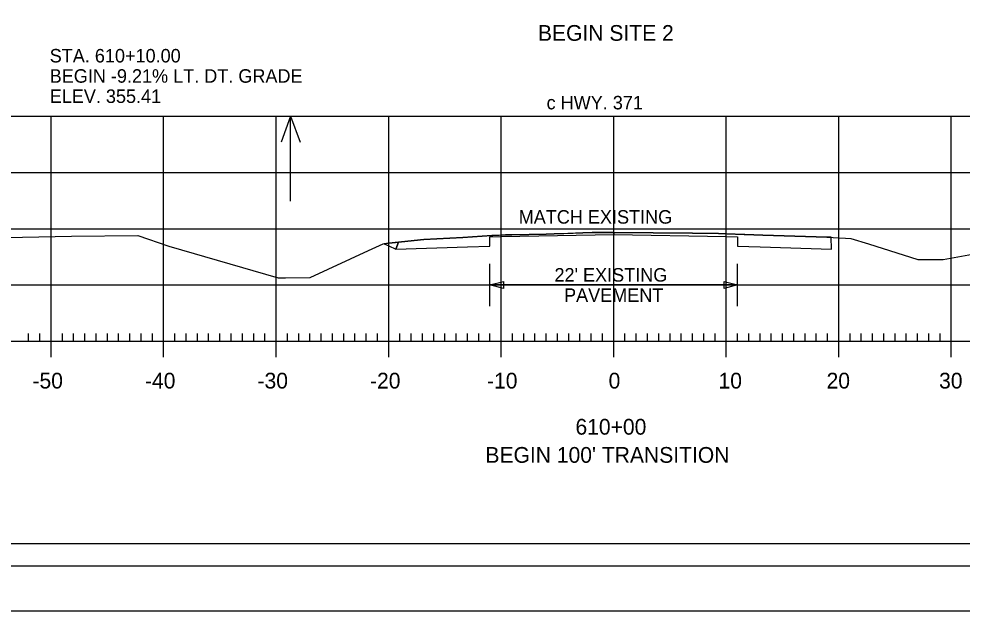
# Model space of a CAD drawing. Extents: x 1368910 to 1369601, y 380116 to 380950.
# Drawn here: x 1369384.7 to 1369468.6, y 380310.4 to 380363.1 of the extents above; entities that cross this region are included whole.
import ezdxf

# ---------------------------------------------------------------- set-up
doc = ezdxf.new("R2010")
doc.units = 0
for name, color, linetype in [('_STAGE 1 CUT', 7, 'Continuous'), ('_STAGE 2 CUT', 7, 'Continuous'), ('Notes', 7, 'Continuous'), ('R_Axis', 7, 'Continuous'), ('R_Axis Annot', 7, 'Continuous'), ('R_Border', 7, 'Continuous'), ('R_Exist Surface', 7, 'Continuous'), ('R_Grid', 7, 'Continuous'), ('R_No Plot', 7, 'Continuous'), ('R_ROW Annot', 7, 'Continuous'), ('R_Water Annot', 7, 'Continuous')]:
    doc.layers.add(name, color=color, linetype=linetype)

msp = doc.modelspace()

# ---------------------------------------------------------------- linework, layer by layer
at = {"layer": '_STAGE 1 CUT'}
for p, q in [((1369437.59, 380343.918), (1369437.59, 380344.085)), ((1369418.228, 380342.615), (1369418.463, 380343.218)), ((1369418.463, 380343.218), (1369418.228, 380342.615))]:
    msp.add_line(p, q, dxfattribs=at)
for points in [[(1369418.228, 380342.615), (1369424.59, 380342.825), (1369426.58, 380342.865), (1369426.59, 380343.698), (1369427.59, 380343.718), (1369437.59, 380343.918)], [(1369437.573, 380344.085), (1369437.254, 380344.088), (1369435.658, 380344.076), (1369434.85, 380344.056), (1369433.509, 380344.004), (1369432.296, 380343.956), (1369431.57, 380343.945), (1369428.535, 380343.893), (1369427.972, 380343.873), (1369427.59, 380343.853), (1369426.844, 380343.815), (1369426.767, 380343.81), (1369424.188, 380343.656), (1369420.71, 380343.461), (1369418.714, 380343.246), (1369418.463, 380343.218)], [(1369437.59, 380344.085), (1369437.59, 380344.085), (1369437.573, 380344.085)], [(1369437.573, 380344.085), (1369437.573, 380344.085)], [(1369418.463, 380343.218), (1369417.59, 380343.124), (1369417.2, 380343.082)], [(1369417.2, 380343.082), (1369417.59, 380342.905), (1369418.228, 380342.615)]]:
    msp.add_lwpolyline(points, dxfattribs=at)
at = {"layer": '_STAGE 2 CUT'}
for p, q in [((1369437.59, 380344.085), (1369437.59, 380343.918)), ((1369456.952, 380342.615), (1369456.924, 380343.657))]:
    msp.add_line(p, q, dxfattribs=at)
for points in [[(1369446.901, 380343.983), (1369444.586, 380344.015), (1369437.59, 380344.085), (1369437.59, 380344.085)], [(1369437.59, 380343.918), (1369447.59, 380343.718), (1369448.59, 380343.698), (1369448.6, 380342.865), (1369450.59, 380342.825), (1369456.952, 380342.615)], [(1369456.924, 380343.657), (1369456.524, 380343.683), (1369450.84, 380343.859), (1369449.227, 380343.914), (1369449.178, 380343.915), (1369447.59, 380343.962), (1369446.901, 380343.983)]]:
    msp.add_lwpolyline(points, dxfattribs=at)
at = {"layer": 'R_Axis'}
for p, q in [((1369385.59, 380334.421), (1369385.59, 380335.121)), ((1369386.59, 380334.421), (1369386.59, 380335.121)), ((1369387.59, 380333.021), (1369387.59, 380335.821)), ((1369388.59, 380334.421), (1369388.59, 380335.121)), ((1369389.59, 380334.421), (1369389.59, 380335.121)), ((1369390.59, 380334.421), (1369390.59, 380335.121)), ((1369391.59, 380334.421), (1369391.59, 380335.121)), ((1369392.59, 380334.421), (1369392.59, 380335.121)), ((1369393.59, 380334.421), (1369393.59, 380335.121)), ((1369394.59, 380334.421), (1369394.59, 380335.121)), ((1369395.59, 380334.421), (1369395.59, 380335.121)), ((1369396.59, 380334.421), (1369396.59, 380335.121)), ((1369397.59, 380333.021), (1369397.59, 380335.821)), ((1369398.59, 380334.421), (1369398.59, 380335.121)), ((1369399.59, 380334.421), (1369399.59, 380335.121)), ((1369400.59, 380334.421), (1369400.59, 380335.121)), ((1369401.59, 380334.421), (1369401.59, 380335.121)), ((1369402.59, 380334.421), (1369402.59, 380335.121)), ((1369403.59, 380334.421), (1369403.59, 380335.121)), ((1369404.59, 380334.421), (1369404.59, 380335.121)), ((1369405.59, 380334.421), (1369405.59, 380335.121)), ((1369406.59, 380334.421), (1369406.59, 380335.121)), ((1369407.59, 380333.021), (1369407.59, 380335.821)), ((1369408.59, 380334.421), (1369408.59, 380335.121)), ((1369409.59, 380334.421), (1369409.59, 380335.121)), ((1369410.59, 380334.421), (1369410.59, 380335.121)), ((1369411.59, 380334.421), (1369411.59, 380335.121)), ((1369412.59, 380334.421), (1369412.59, 380335.121)), ((1369413.59, 380334.421), (1369413.59, 380335.121)), ((1369414.59, 380334.421), (1369414.59, 380335.121)), ((1369415.59, 380334.421), (1369415.59, 380335.121)), ((1369416.59, 380334.421), (1369416.59, 380335.121)), ((1369417.59, 380333.021), (1369417.59, 380335.821)), ((1369418.59, 380334.421), (1369418.59, 380335.121)), ((1369419.59, 380334.421), (1369419.59, 380335.121)), ((1369420.59, 380334.421), (1369420.59, 380335.121)), ((1369421.59, 380334.421), (1369421.59, 380335.121)), ((1369422.59, 380334.421), (1369422.59, 380335.121)), ((1369423.59, 380334.421), (1369423.59, 380335.121)), ((1369424.59, 380334.421), (1369424.59, 380335.121)), ((1369425.59, 380334.421), (1369425.59, 380335.121)), ((1369426.59, 380334.421), (1369426.59, 380335.121)), ((1369427.59, 380333.021), (1369427.59, 380335.821)), ((1369428.59, 380334.421), (1369428.59, 380335.121)), ((1369429.59, 380334.421), (1369429.59, 380335.121)), ((1369430.59, 380334.421), (1369430.59, 380335.121)), ((1369431.59, 380334.421), (1369431.59, 380335.121)), ((1369432.59, 380334.421), (1369432.59, 380335.121)), ((1369433.59, 380334.421), (1369433.59, 380335.121)), ((1369434.59, 380334.421), (1369434.59, 380335.121)), ((1369435.59, 380334.421), (1369435.59, 380335.121)), ((1369436.59, 380334.421), (1369436.59, 380335.121)), ((1369437.59, 380333.021), (1369437.59, 380335.821)), ((1369438.59, 380334.421), (1369438.59, 380335.121)), ((1369439.59, 380334.421), (1369439.59, 380335.121)), ((1369440.59, 380334.421), (1369440.59, 380335.121)), ((1369441.59, 380334.421), (1369441.59, 380335.121)), ((1369442.59, 380334.421), (1369442.59, 380335.121)), ((1369443.59, 380334.421), (1369443.59, 380335.121)), ((1369444.59, 380334.421), (1369444.59, 380335.121)), ((1369445.59, 380334.421), (1369445.59, 380335.121)), ((1369446.59, 380334.421), (1369446.59, 380335.121)), ((1369447.59, 380333.021), (1369447.59, 380335.821)), ((1369448.59, 380334.421), (1369448.59, 380335.121)), ((1369449.59, 380334.421), (1369449.59, 380335.121)), ((1369450.59, 380334.421), (1369450.59, 380335.121)), ((1369451.59, 380334.421), (1369451.59, 380335.121)), ((1369452.59, 380334.421), (1369452.59, 380335.121)), ((1369453.59, 380334.421), (1369453.59, 380335.121)), ((1369454.59, 380334.421), (1369454.59, 380335.121)), ((1369455.59, 380334.421), (1369455.59, 380335.121)), ((1369456.59, 380334.421), (1369456.59, 380335.121)), ((1369457.59, 380333.021), (1369457.59, 380335.821)), ((1369458.59, 380334.421), (1369458.59, 380335.121)), ((1369459.59, 380334.421), (1369459.59, 380335.121)), ((1369460.59, 380334.421), (1369460.59, 380335.121)), ((1369461.59, 380334.421), (1369461.59, 380335.121)), ((1369462.59, 380334.421), (1369462.59, 380335.121)), ((1369463.59, 380334.421), (1369463.59, 380335.121)), ((1369464.59, 380334.421), (1369464.59, 380335.121)), ((1369465.59, 380334.421), (1369465.59, 380335.121)), ((1369466.59, 380334.421), (1369466.59, 380335.121)), ((1369467.59, 380333.021), (1369467.59, 380335.821)), ((1369297.59, 380334.421), (1369577.59, 380334.421))]:
    msp.add_line(p, q, dxfattribs=at)
at = {"layer": 'R_Border'}
msp.add_line((1369595.77, 380314.421), (1369279.59, 380314.421), dxfattribs=at)
at = {"layer": 'R_Exist Surface'}
msp.add_lwpolyline([(1369376.275, 380343.48), (1369389.41, 380343.747), (1369395.306, 380343.805), (1369398.048, 380342.882), (1369407.768, 380340.053), (1369408.416, 380340.07), (1369410.596, 380340.073), (1369415.794, 380342.473), (1369417.092, 380343.07), (1369418.714, 380343.246), (1369420.71, 380343.461), (1369424.188, 380343.656), (1369426.767, 380343.81), (1369426.844, 380343.815), (1369427.972, 380343.873), (1369428.535, 380343.893), (1369431.57, 380343.945), (1369432.296, 380343.956), (1369434.85, 380344.056), (1369435.658, 380344.076), (1369437.254, 380344.088), (1369437.573, 380344.085), (1369444.586, 380344.015), (1369446.901, 380343.983), (1369449.178, 380343.915), (1369449.227, 380343.914), (1369450.84, 380343.859), (1369456.524, 380343.683), (1369458.187, 380343.573), (1369458.66, 380343.562), (1369460.229, 380343.07), (1369464.618, 380341.672), (1369466.096, 380341.68), (1369466.853, 380341.679), (1369470.785, 380342.388)], dxfattribs=at)
at = {"layer": 'R_Grid'}
for p, q in [((1369297.59, 380354.421), (1369577.59, 380354.421)), ((1369387.59, 380334.421), (1369387.59, 380354.421)), ((1369397.59, 380334.421), (1369397.59, 380354.421)), ((1369407.59, 380334.421), (1369407.59, 380354.421)), ((1369417.59, 380334.421), (1369417.59, 380354.421)), ((1369427.59, 380334.421), (1369427.59, 380354.421)), ((1369437.59, 380334.421), (1369437.59, 380354.421)), ((1369447.59, 380334.421), (1369447.59, 380354.421)), ((1369457.59, 380334.421), (1369457.59, 380354.421)), ((1369467.59, 380334.421), (1369467.59, 380354.421)), ((1369297.59, 380349.421), (1369577.59, 380349.421)), ((1369297.59, 380344.421), (1369577.59, 380344.421)), ((1369297.59, 380339.421), (1369577.59, 380339.421)), ((1369297.59, 380334.421), (1369577.59, 380334.421))]:
    msp.add_line(p, q, dxfattribs=at)
at = {"layer": 'R_No Plot'}
for points in [[(1369267.182, 380523.775), (1369600.522, 380523.775), (1369600.522, 380310.438), (1369267.182, 380310.438)], [(1369281.59, 380517.881), (1369531.13, 380517.881), (1369531.13, 380508.001), (1369548.67, 380508.001), (1369572.77, 380508.001), (1369572.77, 380485.668), (1369593.77, 380485.668), (1369593.77, 380316.421), (1369281.59, 380316.421)], [(1369281.59, 380415.151), (1369593.77, 380415.151), (1369593.77, 380316.421), (1369281.59, 380316.421)]]:
    msp.add_lwpolyline(points, close=True, dxfattribs=at)
at = {"layer": 'R_ROW Annot'}
for p, q in [((1369426.59, 380337.537), (1369426.59, 380341.305)), ((1369448.59, 380337.537), (1369448.59, 380341.305)), ((1369448.59, 380339.421), (1369426.59, 380339.421))]:
    msp.add_line(p, q, dxfattribs=at)
for points in [[(1369427.79, 380339.121), (1369426.59, 380339.421), (1369427.79, 380339.721)], [(1369447.39, 380339.721), (1369448.59, 380339.421), (1369447.39, 380339.121)]]:
    msp.add_lwpolyline(points, close=True, dxfattribs=at)
at = {"layer": 'R_Water Annot'}
for p, q in [((1369408.875, 380354.421), (1369408.035, 380352.113)), ((1369408.875, 380346.88), (1369408.875, 380354.421)), ((1369408.875, 380354.421), (1369409.715, 380352.113))]:
    msp.add_line(p, q, dxfattribs=at)

# ---------------------------------------------------------------- texts
at = {"layer": 'Notes'}
for s, p in [('STA. 610+10.00', (1369387.463, 380359.197)), ('BEGIN -9.21% LT. DT. GRADE', (1369387.463, 380357.397)), ('ELEV. 355.41', (1369387.463, 380355.597)), ('c HWY. 371', (1369431.623, 380355.028)), ('MATCH EXISTING', (1369429.144, 380344.872))]:
    msp.add_text(s, height=1.2, dxfattribs=at).set_placement(p)
at = {"layer": 'R_Axis Annot'}
for s, p in [('BEGIN SITE 2', (1369430.855, 380361.121)), ('-50', (1369385.931, 380330.221)), ('-40', (1369395.931, 380330.221)), ('-30', (1369405.931, 380330.221)), ('-20', (1369415.931, 380330.221)), ('-10', (1369426.328, 380330.221)), ('0', (1369437.132, 380330.221)), ('10', (1369446.901, 380330.221)), ('20', (1369456.504, 380330.221)), ('30', (1369466.504, 380330.221)), ('610+00', (1369434.189, 380326.121)), ("BEGIN 100' TRANSITION", (1369426.186, 380323.621))]:
    msp.add_text(s, height=1.4, dxfattribs=at).set_placement(p)
at = {"layer": 'R_ROW Annot'}
for s, p in [("22' EXISTING", (1369432.322, 380339.721)), ('PAVEMENT', (1369433.173, 380337.921))]:
    msp.add_text(s, height=1.2, dxfattribs=at).set_placement(p)

doc.saveas('drawing.dxf')
